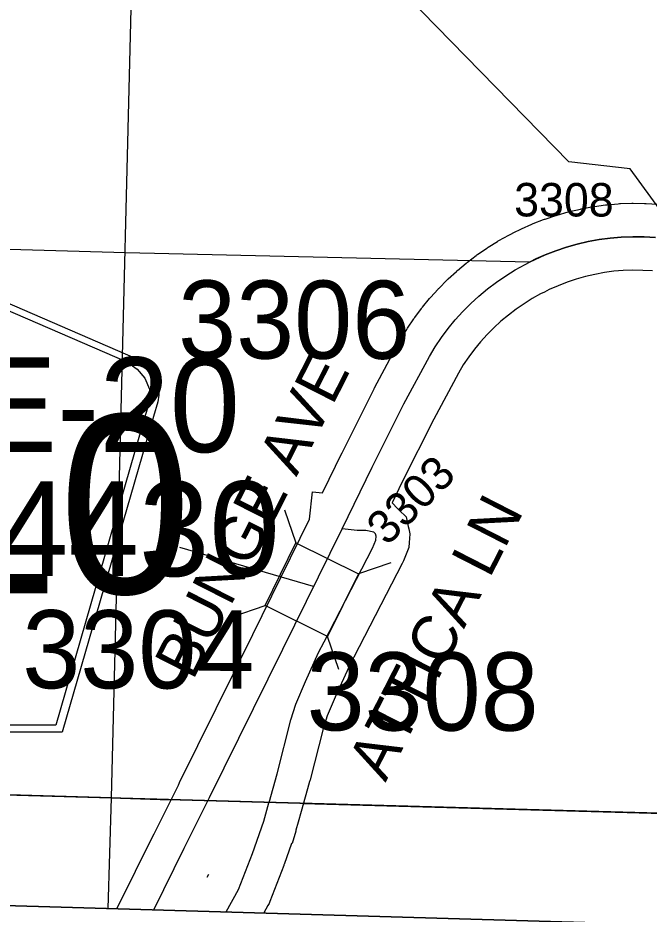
# Model space of a CAD drawing. Extents: x -132.8 to -73.3, y -60 to -26.
# Drawn here: x -120.182 to -119.616, y -56.425 to -55.622 of the extents above; entities that cross this region are included whole.
import ezdxf

# ---------------------------------------------------------------- set-up
doc = ezdxf.new("R2010")
doc.units = 0
for name, color, linetype in [('tdCoClipBndry', 7, 'Continuous'), ('tdCoCoBndry', 7, 'Continuous'), ('tdCoCoBndryPart', 7, 'Continuous'), ('tdCoCorpBndry', 7, 'Continuous'), ('tdCoHydroRiver', 7, 'Continuous'), ('tdCoSecRdNmbr', 7, 'Continuous'), ('tdCoSecRdTxt', 7, 'Continuous'), ('tdCoSecRteBand', 7, 'Continuous'), ('tdCoSecRteCL', 7, 'Continuous'), ('tdCoSectLine', 7, 'Continuous'), ('tdCoSectLinePart', 7, 'Continuous'), ('tdCoShieldCoRteHrd', 7, 'Continuous'), ('tdCoStrucSec', 7, 'Continuous'), ('tdCoStrucSecCoName', 7, 'Continuous'), ('tdCoStrucSecFHWANum', 7, 'Continuous'), ('tdCoSurfAsphalt', 7, 'Continuous'), ('tdCoSurfGravel', 7, 'Continuous'), ('tdCoTwpBndryShd', 7, 'Continuous')]:
    doc.layers.add(name, color=color, linetype=linetype)

msp = doc.modelspace()

# ---------------------------------------------------------------- linework, layer by layer
at = {"layer": 'tdCoClipBndry'}
msp.add_lwpolyline([(-115.13905, -56.56502), (-123.07508, -56.33294)], dxfattribs=at)
at = {"layer": 'tdCoCoBndry'}
for p, q in [((-121.08579, -56.293), (-120.09802, -56.32065)), ((-120.09802, -56.32065), (-121.08579, -56.293)), ((-120.09802, -56.32065), (-120.08995, -56.32121)), ((-120.08995, -56.32121), (-120.09802, -56.32065)), ((-120.08995, -56.32121), (-119.11419, -56.34833)), ((-119.11419, -56.34833), (-120.08995, -56.32121))]:
    msp.add_line(p, q, dxfattribs=at)
for points in [[(-115.13634, -56.46508), (-116.12767, -56.43839), (-117.13423, -56.40832), (-118.12308, -56.37601), (-119.10669, -56.34888), (-119.11419, -56.34833), (-120.08995, -56.32121), (-120.09802, -56.32065), (-121.08579, -56.293), (-122.08264, -56.26323), (-123.07204, -56.23301), (-124.05391, -56.20935), (-124.07538, -56.24979), (-124.09811, -56.29276), (-124.10044, -56.29767), (-124.09926, -56.29863), (-124.0567, -56.30929), (-123.07508, -56.33294), (-115.13905, -56.56502)], [(-105.21445, -56.69742), (-106.20943, -56.67616), (-107.20804, -56.65655), (-108.20651, -56.63735), (-109.20214, -56.61403), (-110.15713, -56.58792), (-111.15481, -56.56114), (-112.14806, -56.53472), (-113.14562, -56.51044), (-114.14283, -56.48785), (-115.13672, -56.46508), (-116.12805, -56.43839), (-117.13461, -56.40832), (-118.12346, -56.37601), (-119.10707, -56.34888), (-119.11457, -56.34833), (-120.09033, -56.32121), (-120.0984, -56.32065), (-121.08617, -56.293), (-122.08302, -56.26323), (-123.07241, -56.23301), (-124.05429, -56.20935)], [(-115.13634, -56.46508), (-116.12767, -56.43839), (-117.13423, -56.40832), (-118.12308, -56.37601), (-119.10669, -56.34888), (-119.11419, -56.34833), (-120.08995, -56.32121), (-120.09802, -56.32065), (-121.08579, -56.293)]]:
    msp.add_lwpolyline(points, dxfattribs=at)
at = {"layer": 'tdCoCoBndryPart'}
for points in [[(-121.05577, -56.29385), (-120.0984, -56.32065), (-120.09033, -56.32121), (-120.04578, -56.32245)], [(-119.92659, -56.32576), (-119.42017, -56.33984)]]:
    msp.add_lwpolyline(points, dxfattribs=at)
at = {"layer": 'tdCoCorpBndry'}
msp.add_lwpolyline([(-119.61028, -55.81864), (-119.62047, -55.81802), (-119.63068, -55.81784), (-119.64089, -55.81811), (-119.6509, -55.81901), (-119.66086, -55.82038), (-119.67074, -55.82221), (-119.68053, -55.8245), (-119.6902, -55.82724), (-119.69973, -55.83043), (-119.7091, -55.83406), (-119.71746, -55.83775), (-119.72319, -55.84057), (-120.0858, -55.83237), (-120.57592, -55.81836)], dxfattribs=at)
at = {"layer": 'tdCoHydroRiver'}
msp.add_lwpolyline([(-119.28377, -56.45743), (-119.28481, -56.43223), (-119.29484, -56.39409), (-119.31979, -56.32399), (-119.34892, -56.29165), (-119.36381, -56.25811), (-119.36953, -56.23587), (-119.38006, -56.21665), (-119.38863, -56.18328), (-119.39929, -56.1688), (-119.42284, -56.10505), (-119.49475, -55.9611), (-119.5507, -55.86965), (-119.63292, -55.75698), (-119.68801, -55.75076), (-119.84625, -55.58872), (-120.05915, -55.58139), (-120.0716, -55.57475), (-120.06611, -55.31139), (-120.29466, -55.29892), (-120.30383, -55.28763), (-120.28819, -54.88097), (-120.29403, -54.86345), (-120.28986, -54.82569)], dxfattribs=at)
at = {"layer": 'tdCoSecRteBand'}
for points in [[(-120.09348, -56.42014), (-120.0599, -56.35262), (-120.05988, -56.35259), (-120.05987, -56.35256), (-120.03856, -56.30994), (-120.0383, -56.30942), (-120.03715, -56.30711), (-119.97138, -56.17426), (-119.92068, -56.07109), (-119.918, -56.04651), (-119.90908, -56.04748), (-119.89121, -56.01112), (-119.89116, -56.01103), (-119.89112, -56.01093), (-119.86273, -55.95415), (-119.86253, -55.95376), (-119.86233, -55.95338), (-119.83955, -55.91094), (-119.83915, -55.9102), (-119.83871, -55.90949), (-119.83347, -55.90091), (-119.83311, -55.90031), (-119.83271, -55.89973), (-119.82708, -55.89141), (-119.82669, -55.89083), (-119.82627, -55.89027), (-119.82025, -55.88222), (-119.81983, -55.88166), (-119.81939, -55.88112), (-119.813, -55.87336), (-119.81256, -55.87282), (-119.81209, -55.8723), (-119.80535, -55.86484), (-119.80488, -55.86433), (-119.80438, -55.86383), (-119.7973, -55.85669), (-119.79681, -55.8562), (-119.7963, -55.85573), (-119.78889, -55.84893), (-119.78837, -55.84846), (-119.78784, -55.84801), (-119.78012, -55.84157), (-119.77959, -55.84112), (-119.77903, -55.84069), (-119.77102, -55.83462), (-119.77047, -55.83419), (-119.76989, -55.8338), (-119.76161, -55.8281), (-119.76103, -55.8277), (-119.76044, -55.82734), (-119.7519, -55.82203), (-119.75131, -55.82166), (-119.7507, -55.82132), (-119.74192, -55.81642), (-119.74131, -55.81608), (-119.74068, -55.81576), (-119.73673, -55.81379), (-119.73659, -55.81372), (-119.73169, -55.81128), (-119.73106, -55.81097), (-119.73042, -55.81068), (-119.72123, -55.80662), (-119.72059, -55.80634), (-119.71994, -55.80608), (-119.71056, -55.80245), (-119.70991, -55.8022), (-119.70925, -55.80198), (-119.69972, -55.79879), (-119.69905, -55.79857), (-119.69838, -55.79838), (-119.68871, -55.79564), (-119.68804, -55.79545), (-119.68736, -55.79529), (-119.67757, -55.793), (-119.67689, -55.79284), (-119.6762, -55.79271), (-119.66632, -55.79088), (-119.66563, -55.79076), (-119.66494, -55.79066), (-119.65498, -55.78929), (-119.65429, -55.7892), (-119.65359, -55.78914), (-119.64358, -55.78823), (-119.64263, -55.78815), (-119.64168, -55.78812), (-119.63148, -55.78785), (-119.63082, -55.78784), (-119.63017, -55.78785), (-119.61996, -55.78802), (-119.6193, -55.78803), (-119.61865, -55.78807), (-119.60845, -55.78869)], [(-119.61276, -55.84854), (-119.62164, -55.848), (-119.63054, -55.84785), (-119.63914, -55.84808), (-119.64751, -55.84883), (-119.65608, -55.85001), (-119.66459, -55.85158), (-119.67302, -55.85355), (-119.68134, -55.85591), (-119.68955, -55.85866), (-119.69762, -55.86178), (-119.70553, -55.86528), (-119.7098, -55.86741), (-119.70995, -55.86748), (-119.70995, -55.86748), (-119.71327, -55.86914), (-119.72083, -55.87336), (-119.72818, -55.87793), (-119.73531, -55.88283), (-119.7422, -55.88806), (-119.74884, -55.89361), (-119.75521, -55.89946), (-119.76131, -55.9056), (-119.76711, -55.91202), (-119.77261, -55.9187), (-119.77779, -55.92563), (-119.78264, -55.9328), (-119.78708, -55.94006), (-119.80925, -55.98137), (-119.83741, -56.03767), (-119.8466, -56.05639), (-119.84166, -56.06133), (-119.84018, -56.06281), (-119.83401, -56.06899), (-119.83211, -56.07751), (-119.83162, -56.07973), (-119.83067, -56.08401), (-119.83098, -56.08838), (-119.83123, -56.09183), (-119.83156, -56.09649), (-119.8333, -56.10083), (-119.83626, -56.10823), (-119.8368, -56.10959), (-119.83747, -56.11088), (-119.88084, -56.19468), (-119.88544, -56.20364), (-119.89681, -56.22852), (-119.90476, -56.24736), (-119.90852, -56.25905), (-119.92018, -56.30456), (-119.92012, -56.30458), (-119.92083, -56.30711), (-119.92083, -56.30711), (-119.92092, -56.30743), (-119.92806, -56.33296), (-119.93072, -56.34245), (-119.93279, -56.34985), (-119.93305, -56.35078), (-119.93614, -56.36185), (-119.93686, -56.36165), (-119.94345, -56.38047), (-119.9436, -56.3809), (-119.94377, -56.38133), (-119.95623, -56.41367), (-119.95696, -56.41555), (-119.95793, -56.41733), (-119.96159, -56.42399)], [(-120.01244, -56.39193), (-120.01149, -56.3902), (-120.01118, -56.3894), (-120.01244, -56.39193)]]:
    msp.add_lwpolyline(points, dxfattribs=at)
at = {"layer": 'tdCoSecRteCL'}
for points in [[(-119.89143, -56.07959), (-119.86429, -56.02435), (-119.83589, -55.96756), (-119.81312, -55.92513), (-119.80787, -55.91656), (-119.80224, -55.90823), (-119.79622, -55.90018), (-119.78983, -55.89242), (-119.78309, -55.88496), (-119.77601, -55.87783), (-119.76861, -55.87103), (-119.76089, -55.86459), (-119.75289, -55.85851), (-119.7446, -55.85282), (-119.73607, -55.84751), (-119.72729, -55.84261), (-119.72334, -55.84064), (-119.7232, -55.84057), (-119.7183, -55.83812), (-119.7091, -55.83406), (-119.69973, -55.83043), (-119.6902, -55.82724), (-119.68053, -55.8245), (-119.67074, -55.82221), (-119.66086, -55.82038), (-119.6509, -55.81901), (-119.64089, -55.81811), (-119.63068, -55.81784), (-119.62047, -55.81802), (-119.61028, -55.81864)], [(-120.01143, -56.32277), (-120.01027, -56.32042), (-119.94447, -56.18753), (-119.89143, -56.07959)], [(-119.95695, -56.32488), (-119.94981, -56.29935), (-119.93735, -56.25073), (-119.93291, -56.23692), (-119.92428, -56.21645), (-119.91244, -56.19056), (-119.90751, -56.18094), (-119.86411, -56.09709), (-119.86115, -56.08969), (-119.8609, -56.08624), (-119.8614, -56.08402), (-119.86288, -56.08254), (-119.87003, -56.08106), (-119.87792, -56.08106), (-119.89143, -56.07959)], [(-120.06045, -56.4211), (-120.03304, -56.36598), (-120.01173, -56.32336)], [(-119.99529, -56.42301), (-119.98422, -56.40288), (-119.97176, -56.37054), (-119.96168, -56.34177), (-119.9571, -56.32539)]]:
    msp.add_lwpolyline(points, dxfattribs=at)
at = {"layer": 'tdCoSectLine'}
for points in [[(-120.0984, -56.32065), (-120.07349, -55.32557)], [(-121.08617, -56.293), (-120.0984, -56.32065)], [(-120.1013, -56.41991), (-120.0984, -56.32065)], [(-120.0984, -56.32065), (-120.09033, -56.32121), (-119.11457, -56.34833)]]:
    msp.add_lwpolyline(points, dxfattribs=at)
at = {"layer": 'tdCoSectLinePart'}
for points in [[(-120.0984, -56.32065), (-120.07349, -55.32557)], [(-121.05577, -56.29385), (-120.0984, -56.32065)], [(-120.1013, -56.41991), (-120.0984, -56.32065)], [(-120.0984, -56.32065), (-120.09033, -56.32121), (-120.04578, -56.32245)], [(-119.92659, -56.32576), (-119.42017, -56.33984)]]:
    msp.add_lwpolyline(points, dxfattribs=at)
at = {"layer": 'tdCoShieldCoRteHrd'}
for points in [[(-120.382, -56.26187), (-120.46394, -55.97898), (-120.46782, -55.96582), (-120.46855, -55.95993), (-120.46855, -55.95211), (-120.46431, -55.9418), (-120.45703, -55.93331), (-120.44746, -55.92664), (-120.28018, -55.85429), (-120.27267, -55.85266), (-120.26224, -55.85174), (-120.25182, -55.85266), (-120.2443, -55.85429), (-120.07703, -55.92664), (-120.06745, -55.93331), (-120.06018, -55.9418), (-120.05593, -55.95211), (-120.05593, -55.95993), (-120.05666, -55.96582), (-120.06054, -55.97898), (-120.14248, -56.26187)], [(-120.37614, -56.25554), (-120.45588, -55.98027), (-120.4596, -55.96763), (-120.4603, -55.96199), (-120.4603, -55.95448), (-120.45622, -55.94458), (-120.44924, -55.93643), (-120.44005, -55.93003), (-120.27946, -55.86057), (-120.27225, -55.859), (-120.26224, -55.85812), (-120.25223, -55.859), (-120.24502, -55.86057), (-120.08443, -55.93003), (-120.07524, -55.93643), (-120.06826, -55.94458), (-120.06419, -55.95448), (-120.06419, -55.96199), (-120.06488, -55.96763), (-120.06861, -55.98027), (-120.14834, -56.25554)]]:
    msp.add_lwpolyline(points, close=True, dxfattribs=at)
at = {"layer": 'tdCoStrucSec'}
for points in [[(-119.94302, -56.06274), (-119.93293, -56.09234), (-119.87678, -56.11993)], [(-119.99012, -56.15858), (-119.96052, -56.14849), (-119.93293, -56.09234)], [(-119.84781, -56.11005), (-119.87678, -56.11993), (-119.90437, -56.17608)], [(-119.89427, -56.20568), (-119.90437, -56.17608), (-119.96052, -56.14849)]]:
    msp.add_lwpolyline(points, dxfattribs=at)
at = {"layer": 'tdCoStrucSecFHWANum'}
msp.add_line((-120.03736, -56.09623), (-119.91725, -56.13103), dxfattribs=at)
at = {"layer": 'tdCoSurfAsphalt'}
for points in [[(-120.01143, -56.32277), (-120.01027, -56.32042), (-119.94447, -56.18753), (-119.89143, -56.07959), (-119.86429, -56.02435), (-119.83589, -55.96756), (-119.81312, -55.92513), (-119.80787, -55.91656), (-119.80224, -55.90823), (-119.79622, -55.90018), (-119.78983, -55.89242), (-119.78309, -55.88496), (-119.77601, -55.87783), (-119.76861, -55.87103), (-119.76089, -55.86459), (-119.75289, -55.85851), (-119.7446, -55.85282), (-119.73607, -55.84751), (-119.72729, -55.84261), (-119.72334, -55.84064), (-119.7232, -55.84057), (-119.7183, -55.83812), (-119.7091, -55.83406), (-119.69973, -55.83043), (-119.6902, -55.82724), (-119.68053, -55.8245), (-119.67074, -55.82221), (-119.66086, -55.82038), (-119.6509, -55.81901), (-119.64089, -55.81811), (-119.63068, -55.81784), (-119.62047, -55.81802), (-119.61028, -55.81864)], [(-120.06045, -56.4211), (-120.03304, -56.36598), (-120.01173, -56.32336)]]:
    msp.add_lwpolyline(points, dxfattribs=at)
at = {"layer": 'tdCoSurfGravel'}
for points in [[(-119.95695, -56.32488), (-119.94981, -56.29935), (-119.93735, -56.25073), (-119.93291, -56.23692), (-119.92428, -56.21645), (-119.91244, -56.19056), (-119.90751, -56.18094), (-119.86411, -56.09709), (-119.86115, -56.08969), (-119.8609, -56.08624), (-119.8614, -56.08402), (-119.86288, -56.08254), (-119.87003, -56.08106), (-119.87792, -56.08106), (-119.89143, -56.07959)], [(-119.99529, -56.42301), (-119.98422, -56.40288), (-119.97176, -56.37054), (-119.96168, -56.34177), (-119.9571, -56.32539)]]:
    msp.add_lwpolyline(points, dxfattribs=at)
at = {"layer": 'tdCoTwpBndryShd'}
msp.add_lwpolyline([(-105.21445, -56.69742), (-106.20943, -56.67616), (-107.20804, -56.65655), (-108.20651, -56.63735), (-109.20214, -56.61403), (-110.15713, -56.58792), (-111.15481, -56.56114), (-112.14806, -56.53472), (-113.14562, -56.51044), (-114.14283, -56.48785), (-115.13672, -56.46508), (-116.12805, -56.43839), (-117.13461, -56.40832), (-118.12346, -56.37601), (-119.10707, -56.34888), (-119.11457, -56.34833), (-120.09033, -56.32121), (-120.0984, -56.32065), (-121.08617, -56.293), (-122.08302, -56.26323), (-123.07241, -56.23301), (-124.05429, -56.20935)], dxfattribs=at)

# ---------------------------------------------------------------- texts
at = {"layer": 'tdCoSecRdNmbr'}
for s, height, rotation, p in [('3308', 0.03, 359.91086, (-119.73704, -55.79962)), ('3306', 0.07, 359.91086, (-120.03858, -55.92698)), ('3303', 0.03, 44.91074, (-119.85103, -56.0957)), ('3304', 0.07, 359.91079, (-120.17841, -56.22251)), ('3308', 0.07, 359.91085, (-119.9233, -56.26027))]:
    msp.add_text(s, height=height, rotation=rotation, dxfattribs=at).set_placement(p)
at = {"layer": 'tdCoSecRdTxt'}
for s, rotation, p in [('BUNGE AVE', 63.04555, (-120.02537, -56.2163)), ('ATTICA LN', 62.93561, (-119.85245, -56.30741))]:
    msp.add_text(s, height=0.04, rotation=rotation, dxfattribs=at).set_placement(p)
at = {"layer": 'tdCoShieldCoRteHrd'}
msp.add_text('H10', height=0.16, dxfattribs=at).set_placement((-120.41898, -56.13761))
at = {"layer": 'tdCoStrucSecCoName'}
msp.add_text('LE-20', height=0.085, dxfattribs=at).set_placement((-120.28622, -56.01092))
at = {"layer": 'tdCoStrucSecFHWANum'}
msp.add_text('364430', height=0.085, dxfattribs=at).set_placement((-120.32655, -56.12205))

doc.saveas('drawing.dxf')
